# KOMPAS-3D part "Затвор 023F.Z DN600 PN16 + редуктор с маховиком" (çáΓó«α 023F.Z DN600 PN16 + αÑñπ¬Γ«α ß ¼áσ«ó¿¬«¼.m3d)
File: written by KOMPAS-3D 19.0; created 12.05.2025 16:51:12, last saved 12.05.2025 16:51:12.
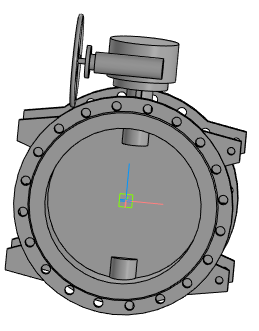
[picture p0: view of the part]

Document properties: Полное имя файла: Затвор 023F.Z DN600 PN16 + редуктор с маховиком.a3d

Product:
- Part/product: Затвор 023F.Z DN600 PN16 + редуктор с маховиком
    Масса: 480.484

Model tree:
1. Операция без истории:1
